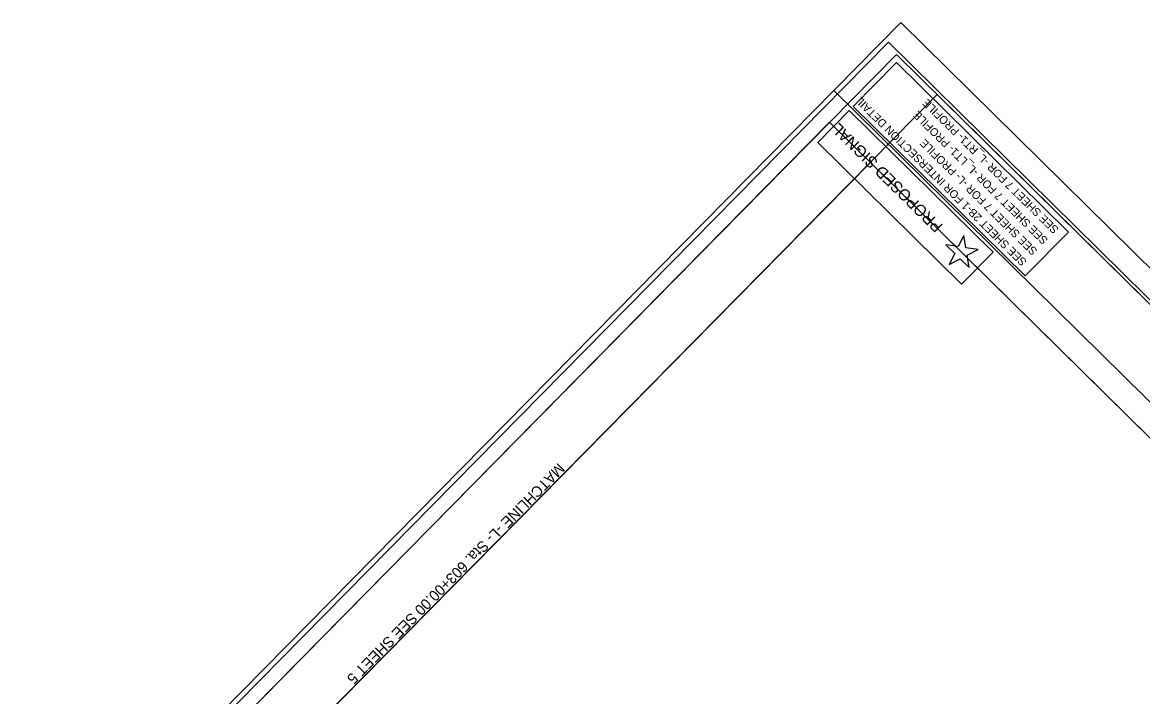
# Model space of a CAD drawing. Extents: x 1266642 to 1268668, y 770349 to 772370.
# Drawn here: x 1266701 to 1267681, y 771780 to 772370 of the extents above; entities that cross this region are included whole.
import ezdxf

# ---------------------------------------------------------------- set-up
doc = ezdxf.new("R2010")
doc.units = 0
for name, color, linetype in [('COGO Default Chain', 7, 'Continuous'), ('Exist Utilities Other Pole CELL', 7, 'Continuous'), ('Exist Utilities Other Pole Cogo Elevation', 7, 'Continuous'), ('Exist Utilities Other Pole Cogo Number', 7, 'Continuous'), ('Exist Utilities Power Pole CELL', 7, 'Continuous'), ('Exist Utilities Sanitary Sewer Manhole Cogo Number', 7, 'Continuous'), ('Prop Conc 1ft 6in Curb and Gutter', 7, 'Continuous'), ('Prop Conc 4in Sidewalk', 7, 'Continuous'), ('Prop EOT', 7, 'Continuous'), ('Prop Horizontal Alignment Station Label', 7, 'Continuous'), ('Prop Plan Preparation Crest', 7, 'Continuous'), ('Prop Plan Preparation Watershed Post Construction', 7, 'Continuous'), ('Typical Terminator CELL', 7, 'Continuous')]:
    doc.layers.add(name, color=color, linetype=linetype)

msp = doc.modelspace()

# ---------------------------------------------------------------- linework, layer by layer
at = {"layer": 'COGO Default Chain'}
msp.add_line((1266898.55, 771695.25), (1267249.48, 772051.41), dxfattribs=at)
at = {"layer": 'Exist Utilities Other Pole CELL'}
msp.add_lwpolyline([(1267521.13, 772162.97), (1267528.88, 772155.33), (1267527.09, 772166.07), (1267536.77, 772171.09), (1267525.99, 772172.72), (1267524.2, 772183.46), (1267519.33, 772173.72), (1267508.56, 772175.34), (1267516.32, 772167.7), (1267511.45, 772157.94), (1267521.13, 772162.97)], dxfattribs=at)
at = {"layer": 'Exist Utilities Other Pole Cogo Number'}
msp.add_lwpolyline([(1267522.21, 772140.78), (1267396.45, 772264.7), (1267424.06, 772292.72), (1267549.82, 772168.8)], close=True, dxfattribs=at)
at = {"layer": 'Exist Utilities Power Pole CELL'}
msp.add_lwpolyline([(1267796.95, 770541.08), (1268533.89, 771289.02), (1267501.02, 772306.72), (1266885.88, 771682.41), (1266992.76, 771577.1), (1266870.95, 771453.46)], close=True, dxfattribs=at)
at = {"layer": 'Prop Conc 1ft 6in Curb and Gutter'}
for points in [[(1266728.44, 771593.89), (1267796.95, 770541.08), (1268533.89, 771289.02), (1267465.41, 772341.81)], [(1267615.97, 772186.44), (1267465.46, 772334.74), (1267427.56, 772296.28), (1267578.08, 772147.98)]]:
    msp.add_lwpolyline(points, close=True, dxfattribs=at)
at = {"layer": 'Prop Conc 4in Sidewalk'}
msp.add_line((1268609.75, 771128.79), (1267410.56, 772310.37), dxfattribs=at)
at = {"layer": 'Prop EOT'}
msp.add_lwpolyline([(1268644.99, 771183.08), (1267458.27, 772352.36), (1266717.81, 771600.88), (1267904.53, 770431.59)], close=True, dxfattribs=at)
at = {"layer": 'Prop Horizontal Alignment Station Label'}
msp.add_lwpolyline([(1268668.29, 771188.2), (1267469.1, 772369.78), (1266700.57, 771589.79), (1267899.75, 770408.22)], close=True, dxfattribs=at)
at = {"layer": 'Prop Plan Preparation Crest'}
msp.add_lwpolyline([(1267738.44, 770481.67), (1268475.35, 771229.61), (1267406.88, 772282.39), (1266818.36, 771685.1), (1266988.78, 771517.18), (1266840.35, 771366.54)], close=True, dxfattribs=at)
at = {"layer": 'Prop Plan Preparation Watershed Post Construction'}
msp.add_lwpolyline([(1268439.74, 771264.7), (1267442.48, 772247.31), (1266853.97, 771650.02), (1266988.78, 771517.18), (1266840.35, 771366.54), (1267702.79, 770516.76)], close=True, dxfattribs=at)
at = {"layer": 'Typical Terminator CELL'}
msp.add_lwpolyline([(1268439.74, 771264.7), (1267442.48, 772247.31), (1266853.97, 771650.02), (1266988.78, 771517.18), (1266840.35, 771366.54), (1267702.79, 770516.76)], close=True, dxfattribs=at)

# ---------------------------------------------------------------- texts
at = {"layer": 'COGO Default Chain'}
msp.add_text('MATCHLINE -L- Sta. 603+00.00 SEE SHEET 5', height=9.375, rotation=225.42732, dxfattribs=at).set_placement((1267169.36, 771985.07))
at = {"layer": 'Exist Utilities Other Pole Cogo Elevation'}
msp.add_text('PROPOSED SIGNAL', height=10, rotation=135.42387, dxfattribs=at).set_placement((1267506.55, 772192.3))
at = {"layer": 'Exist Utilities Sanitary Sewer Manhole Cogo Number'}
for s, p in [('SEE SHEET 2B-1 FOR INTERSECTION DETAIL', (1267579.82, 772161)), ('SEE SHEET 7 FOR -L_RT1- PROFILE', (1267607.77, 772189.26)), ('SEE SHEET 7 FOR -L_LT1- PROFILE', (1267598.45, 772179.84)), ('SEE SHEET 7 FOR -L- PROFILE', (1267589.13, 772170.42))]:
    msp.add_text(s, height=7, rotation=135.31046, dxfattribs=at).set_placement(p)

doc.saveas('drawing.dxf')
